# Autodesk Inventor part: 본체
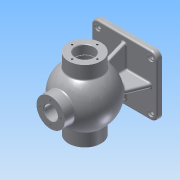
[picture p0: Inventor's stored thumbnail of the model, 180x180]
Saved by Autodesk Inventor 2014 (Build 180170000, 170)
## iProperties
Created: 2017-01
Part Number: 본체
Material: Aluminum 6061
Document SubType Name: Modeling
Designer: ksu
Density: 2.71 g/cm^3
Appearance: Aluminum - Flat
Mass: 1509 g
Surface Area: 1155.11 cm^2
Volume: 556.828 cm^3
Author: ksu
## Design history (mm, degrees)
sketch "Sketch1"
  geometry: L1 (-62.5, -57.5)-(62.5, -57.5); L2 (62.5, -57.5)-(62.5, 57.5); L3 (62.5, 57.5)-(-62.5, 57.5); L4 (-62.5, 57.5)-(-62.5, -57.5); L5 (-62.5, -57.5)-(62.5, 57.5); L6 (62.5, -57.5)-(-62.5, 57.5); 1 further point
  constraints: 12 end point, 2 midpoint, 2 parallel, 1 horizontal, 1 perpendicular
  dimensions: "d0" = 125 distance of L3.end L2.end; "d1" = 115 distance of L2.end L1.end
extrude "Extrusion1" new body sketch "Sketch1" distance "d2" = 10; taper "d3" = 0 deg
sketch "Sketch2"
  geometry: L1 (-57.5, 0)-(57.5, 0) reference; L2 (-68, 85)-(106.185, 85); L3 (-68, 116)-(-68, 102.5); L4 (68, 116)-(68, 102.5); L5 (-68, 116)-(-42.988, 116); L6 (42.988, 116)-(68, 116); L7 (-68, 102.5)-(-39.278, 102.5); L8 (39.278, 102.5)-(68, 102.5); A1 r 53 centre (0, 85) between (42.988, 116) and (-42.988, 116); A2 r 43 centre (0, 85) between (39.278, 102.5) and (-39.278, 102.5); 1 further point
  constraints: 14 end point, 6 parallel, 4 point on circle, 2 centre point, 1 coincident
  dimensions: "d4" = 106 diameter of A1; "d5" = 86 diameter of A2; "d6" = 85 distance from line of L1 A2.centre; "d9" = 136 distance of L3.start L4.start; "d10" = 68 horizontal distance of point (0, 0) L4.start; "d11" = 136 distance of L3.end L4.end; "d12" = 68 horizontal distance of point (0, 0) L4.end
revolve "Revolution1" sketch "Sketch2" stored, may be unused: angle "d13" = 90 deg
workplane "Work Plane1"
sketch "Sketch3"
  geometry: C1 r 27 at (0, 0); 1 further point
  constraints: 1 centre point, 1 coincident
  dimensions: "d15" = 54 diameter of C1
extrude "Extrusion2" join sketch "Sketch3" distance "d16" = 30; taper "d17" = 0 deg
sketch "Sketch4"
  geometry: C1 r 27 at (0, 0) reference; C2 r 13 at (0, 0)
  constraints: 1 centre point, 1 coincident
  dimensions: "d18" = 26 diameter of C2
extrude "Extrusion3" cut sketch "Sketch4" distance "d19" = 30; taper "d20" = 0 deg
sketch "Sketch5"
  geometry: L1 (62.5, 10)-(-62.5, 10) reference; L2 (-35.008, 53.295)-(-52.5, 10); L3 (35.008, 53.295)-(52.5, 10); L4 (-52.5, 10)-(52.5, 10); L5 (-62.5, 0)-(-62.5, 10) reference; L6 (62.5, 0)-(62.5, 10) reference; A1 r 47.231 centre (0, 85) between (-35.008, 53.295) and (35.008, 53.295); 3 further points
  constraints: 6 end point, 4 point on line, 2 point on circle, 1 centre point, 1 collinear
  dimensions: "d21" = 10 distance of L1.end L2.end; "d22" = 10 distance of L1.start L3.end; "d23" = 22 deg angle of L5 L2; "d24" = 22 deg angle of L6 L3
extrude "Extrusion4" join sketch "Sketch5" stored distance "d25" = 8; taper "d26" = 0 deg
sketch "Sketch6"
  geometry: L1 (57.5, 10)-(-57.5, 10) reference; L2 (-30.87, 51.162)-(-47.5, 10); L3 (30.87, 51.162)-(47.5, 10); L4 (-47.5, 10)-(47.5, 10); L5 (-57.5, 0)-(-57.5, 10) reference; L6 (57.5, 0)-(57.5, 10) reference; A1 r 45.804 centre (0, 85) between (-30.87, 51.162) and (30.87, 51.162); 1 further point
  constraints: 6 end point, 2 point on circle, 2 point on line, 1 centre point, 1 collinear
  dimensions: "d27" = 10 distance of L1.end L2.end; "d28" = 10 distance of L1.start L3.end; "d29" = 22 deg angle of L5 L2; "d30" = 22 deg angle of L6 L3
extrude "Extrusion5" join sketch "Sketch6" stored distance "d31" = 8; taper "d32" = 0 deg
fillet "Fillet1" dims "d33" = 12
sketch "Sketch7"
  geometry: A1 r 12 centre (-50.5, 45.5) between (-50.5, 57.5) and (-62.5, 45.5) reference; A2 r 12 centre (-50.5, -45.5) between (-62.5, -45.5) and (-50.5, -57.5) reference; A3 r 12 centre (50.5, -45.5) between (50.5, -57.5) and (62.5, -45.5) reference; A4 r 12 centre (50.5, 45.5) between (62.5, 45.5) and (50.5, 57.5) reference; 5 further points
  constraints: 4 coincident
hole "Hole1" sketch "Sketch7" at (-50.5, 45.5), (50.5, 45.5), (50.5, -45.5), (-50.5, -45.5) diameter "d34" = 8; stored, may be unused: countersink angle "d38" = 90 deg, drill point angle "d40" = 118 deg; dims "d35" = 6, "d36" = 12, "d37" = 3, "d39" = 10
sketch "Sketch8" dims "d41" = 45
  geometry: C1 r 31 at (0, 0) reference; 3 further points
  constraints: 1 coincident, 1 vertical alignment, 2 other
hole "Hole2" sketch "Sketch8" at (0, 22.5) diameter "d42" = 3.459; stored, may be unused: countersink angle "d46" = 90 deg, drill point angle "d48" = 118 deg; dims "d43" = 12, "d44" = 12, "d45" = 3, "d47" = 15
workaxis "Work Axis1"
pattern_circular "Circular Pattern1" dims angle "d50" = 360 deg
sketch "Sketch9" dims "d52" = 48
  geometry: C1 r 17.5 at (0, 0) reference; 3 further points
  constraints: 1 coincident, 1 vertical alignment, 2 other
hole "Hole3" sketch "Sketch9" at (0, 24) diameter "d53" = 3.459; stored, may be unused: countersink angle "d57" = 90 deg, drill point angle "d59" = 118 deg; dims "d54" = 16, "d55" = 12, "d56" = 3, "d58" = 19
pattern_circular "Circular Pattern2" dims angle "d61" = 360 deg
workplane "Work Plane2"
sketch "Sketch10"
  geometry: L1 (142.729, 66.239)-(142.729, 24.761); L2 (142.729, 24.761)-(137.271, 24.761); L3 (137.271, 24.761)-(137.271, 66.239); L4 (137.271, 66.239)-(142.729, 66.239); L5 (140, 66.239)-(140, 24.761); L6 (142.729, 45.5)-(137.271, 45.5); L7 (150, 72.5)-(130.607, 72.5) reference; 1 further point
  constraints: 4 end point, 4 midpoint, 2 other
  dimensions: "d64" = 27 distance from line of L7.start L6; "d65" = 10 distance from line of L7.start L5
emboss "Emboss1" sketch "Sketch10" dims "d0" = 125, "d1" = 115, "d66" = 0.5, "d67" = 0
sketch "Sketch11"
  geometry: L1 (-27.094, 118.39)-(-27.094, 85); L2 (-27.094, 85)-(31.416, 85); L3 (31.416, 85)-(31.543, 114.224); L4 (-95.2, 85)-(95.2, 85) reference; A1 r 43 centre (0, 85) between (-24.98, 120) and (24.98, 120) reference; A2 r 43 centre (0, 85) between (31.543, 114.224) and (-27.094, 118.39); 1 further point
  constraints: 6 end point, 4 point on circle, 1 centre point, 1 coincident, 1 concentric, 1 perpendicular, 1 vertical
revolve "Revolution2" sketch "Sketch11" stored, may be unused: angle "d68" = 90 deg
chamfer "Chamfer1" distance "d69" = 1; stored, may be unused: second distance "d70" = 2, angle "d71" = 45 deg
sketch "Sketch12"
  geometry: L1 (50.25, 103.5)-(52, 103.5); L2 (52, 103.5)-(52, 85); L3 (52, 85)-(50.25, 85); L4 (50.25, 85)-(50.25, 103.5); L5 (45.5, 0)-(-45.5, 0) reference; L6 (68, 66.5)-(68, 103.5) reference; L7 (-95.2, 85)-(95.2, 85) reference; 1 further point
  constraints: 8 end point, 2 parallel, 1 horizontal, 1 perpendicular
  dimensions: "d72" = 85 distance between parallel lines of L5 L3; "d73" = 1.75 distance of L1.start L1.end; "d74" = 16 distance between parallel lines of L6 L2; "d76" = 18.5 distance between parallel lines of L3 L1
revolve "Revolution3" sketch "Sketch12" stored, may be unused: angle "d75" = 90 deg
sketch "Sketch13" dims "d77" = 40
  geometry: C1 r 27 at (0, 0) reference; 2 further points
  constraints: 1 coincident, 1 vertical alignment, 2 other
hole "Hole4" sketch "Sketch13" at (0, 20) diameter "d78" = 3.459; stored, may be unused: countersink angle "d82" = 90 deg, drill point angle "d84" = 118 deg; dims "d79" = 9, "d80" = 12, "d81" = 3, "d83" = 11
workaxis "Work Axis2"
pattern_circular "Circular Pattern3" dims angle "d86" = 360 deg
fillet "Fillet2" dims "d88" = 3
fillet "Fillet3" dims "d89" = 3
fillet "Fillet4" dims "d90" = 3
fillet "Fillet5" dims "d91" = 3
fillet "Fillet6" dims "d92" = 3
fillet "Fillet7" dims "d93" = 3
chamfer "Chamfer2" distance "d94" = 1; stored, may be unused: second distance "d95" = 2, angle "d96" = 45 deg
body "Solid1"
other parameters: "d7" = 62, "d8" = 35
